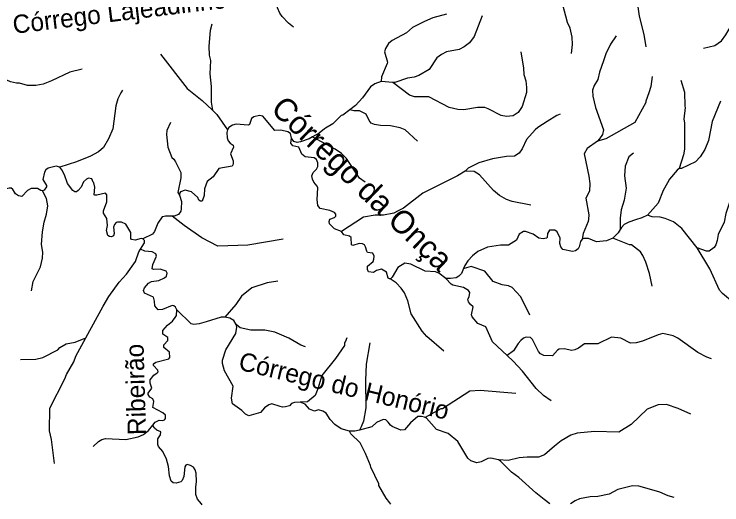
# Model space of a CAD drawing. Extents: x 393 to 446.6, y 8175.5 to 8231.
# Drawn here: x 430.63 to 436.82, y 8175.63 to 8179.91 of the extents above; entities that cross this region are included whole.
import ezdxf
from ezdxf.enums import TextEntityAlignment as Align

# ---------------------------------------------------------------- set-up
doc = ezdxf.new("R2010")
doc.units = 0
doc.header["$LTSCALE"] = 0.064
doc.linetypes.add('LONG_DASHED', pattern=[7.5, 6, -1.5])
doc.layers.add('61', color=7, linetype='Continuous')
doc.layers.add('7', color=7, linetype='Continuous', lineweight=25)
doc.layers.add('9', color=7, linetype='LONG_DASHED', lineweight=25)

msp = doc.modelspace()

# ---------------------------------------------------------------- linework, layer by layer
at = {"layer": '7'}
for points in [[(431.2298, 8179.431), (431.12, 8179.4063), (430.9618, 8179.3287), (430.8875, 8179.2997), (430.8229, 8179.29), (430.7518, 8179.29), (430.6808, 8179.3094), (430.655, 8179.3094), (430.6033, 8179.3223), (430.5387, 8179.3514), (430.5177, 8179.3772), (430.5015, 8179.4402), (430.4983, 8179.5888), (430.4934, 8179.6146), (430.4696, 8179.6566)], [(431.5806, 8179.2495), (431.567, 8179.2242), (431.5398, 8179.1738), (431.5221, 8179.1108), (431.4979, 8178.9106), (431.4591, 8178.8234), (431.4139, 8178.7474), (431.3703, 8178.7103), (431.3009, 8178.6731), (431.1782, 8178.6231), (431.033, 8178.5775)], [(431.033, 8178.5775), (431.0004, 8178.5844), (430.9327, 8178.5666), (430.9117, 8178.5537), (430.8988, 8178.5327), (430.8859, 8178.4697), (430.9181, 8178.4164), (430.9181, 8178.4035), (430.897, 8178.3751), (430.883, 8178.3693)], [(431.7583, 8177.9509), (431.7432, 8177.9521), (431.692, 8177.9393), (431.6593, 8177.9433), (431.6529, 8177.9529), (431.6529, 8178.0062), (431.6093, 8178.0773), (431.5722, 8178.0967), (431.5366, 8178.0967), (431.5269, 8178.0918), (431.5108, 8178.0757), (431.5011, 8178.0531), (431.5075, 8177.9966), (431.5027, 8177.9756), (431.4849, 8177.9691), (431.4688, 8177.9707), (431.4526, 8177.9804), (431.4413, 8178.0224), (431.451, 8178.0676), (431.4446, 8178.129), (431.4139, 8178.1742), (431.4155, 8178.1936), (431.4446, 8178.2743), (431.443, 8178.334), (431.4316, 8178.3502), (431.3558, 8178.3324), (431.3396, 8178.3308), (431.3348, 8178.3357), (431.338, 8178.4003), (431.3299, 8178.4406), (431.3234, 8178.4438), (431.3138, 8178.4746), (431.2831, 8178.4794), (431.2654, 8178.4713), (431.2411, 8178.4471), (431.2185, 8178.4019), (431.1943, 8178.3728), (431.1797, 8178.3599), (431.1652, 8178.3599), (431.1475, 8178.3712), (431.1006, 8178.4326), (431.0748, 8178.5101), (431.0522, 8178.5536), (431.033, 8178.5775)], [(430.883, 8178.3693), (430.8679, 8178.3716), (430.839, 8178.3889), (430.7825, 8178.3906), (430.7518, 8178.3728), (430.7018, 8178.3211), (430.6711, 8178.326), (430.6452, 8178.3437), (430.621, 8178.3857), (430.6146, 8178.3857), (430.613, 8178.3922), (430.5904, 8178.3922), (430.5452, 8178.3809), (430.5257, 8178.3664), (430.4822, 8178.3098), (430.4192, 8178.3098), (430.3578, 8178.3502), (430.2771, 8178.3744), (430.2381, 8178.3946)], [(430.7866, 8177.4953), (430.8003, 8177.5767), (430.8649, 8177.7059), (430.8826, 8177.7802), (430.8842, 8177.8351), (430.8745, 8177.8997), (430.8826, 8178.0127), (430.8955, 8178.0967), (430.9181, 8178.1645), (430.9294, 8178.2388), (430.9165, 8178.3034), (430.883, 8178.3693)], [(431.7389, 8177.8589), (431.7724, 8177.9158), (431.7723, 8177.9358), (431.7583, 8177.9509)], [(431.2609, 8177.0865), (431.4106, 8177.3636), (431.4623, 8177.4476), (431.5527, 8177.5719), (431.6173, 8177.6429), (431.6948, 8177.7511), (431.7239, 8177.8383), (431.7389, 8177.8589)], [(432.0558, 8177.3301), (432.0453, 8177.3539), (432.0291, 8177.3668), (432.0162, 8177.3684), (431.9306, 8177.3329), (431.8935, 8177.3313), (431.8628, 8177.3652), (431.8612, 8177.4056), (431.8515, 8177.4411), (431.7724, 8177.475), (431.7659, 8177.4992), (431.774, 8177.5218), (431.8079, 8177.5622), (431.8338, 8177.5767), (431.8983, 8177.588), (431.9468, 8177.609), (431.9645, 8177.6235), (431.971, 8177.651), (431.9629, 8177.6671), (431.9113, 8177.6849), (431.8531, 8177.6817), (431.8402, 8177.6897), (431.8466, 8177.7269), (431.8773, 8177.7996), (431.8725, 8177.8206), (431.8402, 8177.8367), (431.7756, 8177.8432), (431.7389, 8177.8589)], [(431.8475, 8176.3228), (431.8661, 8176.3507), (431.9016, 8176.3672), (431.9339, 8176.364), (431.9484, 8176.3688), (431.9564, 8176.3818), (431.9564, 8176.4092), (431.9322, 8176.4302), (431.8466, 8176.4771), (431.8547, 8176.5304), (431.845, 8176.553), (431.8208, 8176.5675), (431.8047, 8176.5917), (431.8047, 8176.6014), (431.8386, 8176.645), (431.824, 8176.6886), (431.824, 8176.7192), (431.8547, 8176.7613), (431.8838, 8176.779), (431.8919, 8176.7903), (431.8902, 8176.8032), (431.8515, 8176.8436), (431.8531, 8176.8581), (431.8725, 8176.8743), (431.9872, 8176.9033), (431.9936, 8176.9146), (431.992, 8176.9599), (431.9435, 8177.0018), (431.9419, 8177.0261), (431.9774, 8177.0616), (431.9774, 8177.0874), (431.9338, 8177.1181), (431.9338, 8177.1504), (431.9742, 8177.1956), (432.0178, 8177.2311), (432.0404, 8177.2635), (432.0517, 8177.2812), (432.0558, 8177.3301)], [(430.6888, 8176.8976), (430.8229, 8176.8985), (430.8843, 8176.9146), (431.0167, 8176.9825), (431.0344, 8177.0002), (431.0877, 8177.0325), (431.1685, 8177.0487), (431.2609, 8177.0865)], [(430.9873, 8175.9886), (430.9601, 8176.1977), (430.944, 8176.2752), (430.9472, 8176.4706), (431.078, 8176.7274), (431.0925, 8176.7661), (431.1571, 8176.8759), (431.1733, 8176.9244), (431.2609, 8177.0865)], [(431.3254, 8176.136), (431.3703, 8176.1799), (431.401, 8176.1977), (431.4333, 8176.2074), (431.6109, 8176.1977), (431.7175, 8176.2204), (431.764, 8176.2425), (431.8077, 8176.2768), (431.8475, 8176.3228)], [(432.2769, 8175.6276), (432.27, 8175.636), (432.2358, 8175.6777), (432.2229, 8175.7165), (432.2213, 8175.7811), (432.2277, 8175.8328), (432.2245, 8175.9038), (432.2164, 8175.9329), (432.2003, 8175.9571), (432.1761, 8175.9716), (432.147, 8175.9797), (432.1347, 8175.9749), (432.1244, 8175.9587), (432.1163, 8175.8747), (432.1018, 8175.8408), (432.0905, 8175.8295), (432.0501, 8175.8166), (432.0243, 8175.8198), (432.0065, 8175.8344), (431.9904, 8175.8812), (431.9839, 8175.9619), (431.9645, 8176.0265), (431.9338, 8176.0944), (431.8967, 8176.1363), (431.8902, 8176.1557), (431.8902, 8176.2025), (431.9128, 8176.2397), (431.9161, 8176.2639), (431.8822, 8176.2784), (431.8603, 8176.296), (431.8475, 8176.3228)]]:
    msp.add_lwpolyline(points, dxfattribs=at)
at = {"layer": '9'}
msp.add_line((433.9444, 8179.3147), (433.8419, 8179.3252), dxfattribs=at)
for points in [[(436.1585, 8179.6271), (436.1388, 8179.7341), (436.0984, 8179.8956), (436.0726, 8180.0894), (436.0435, 8180.1717), (436.0176, 8180.225), (435.9886, 8180.3219), (435.9466, 8180.422), (435.8982, 8180.5738), (435.882, 8180.6428)], [(433.0745, 8179.7991), (433.0303, 8179.8342), (432.977, 8179.8907), (432.956, 8179.9214), (432.9367, 8179.9682), (432.9189, 8180.0506), (432.909, 8180.2268), (432.8672, 8180.4074)], [(435.5056, 8179.57), (435.5137, 8179.6468), (435.5106, 8179.7115), (435.4945, 8179.7906), (435.4686, 8179.8407), (435.4299, 8179.9925), (435.4218, 8180.0571), (435.4153, 8180.0651)], [(436.6586, 8179.6162), (436.7565, 8179.6383), (436.8147, 8179.6802), (436.8543, 8179.7331), (436.9359, 8179.8716), (436.9736, 8179.9069), (437.0414, 8179.9424), (437.0661, 8179.9476), (437.1254, 8179.9602), (437.1803, 8179.9892), (437.241, 8180.0438)], [(434.4134, 8179.9117), (434.2915, 8179.8794), (434.2204, 8179.8487), (434.1381, 8179.8084), (434.1155, 8179.7955), (434.0621, 8179.7486), (433.9362, 8179.6824), (433.9055, 8179.6566), (433.878, 8179.6114), (433.8716, 8179.5839), (433.8958, 8179.4935), (433.8942, 8179.4822), (433.8458, 8179.3659), (433.8419, 8179.3252)], [(434.7239, 8179.8977), (434.6532, 8179.718), (434.6128, 8179.6614), (434.5676, 8179.6275), (434.524, 8179.6049), (434.411, 8179.5823), (434.369, 8179.5613), (434.3286, 8179.5306), (434.2608, 8179.4305), (434.172, 8179.3772), (434.13, 8179.361), (434.0702, 8179.353), (433.962, 8179.3158), (433.9444, 8179.3147)], [(432.3621, 8179.8243), (432.3472, 8179.7696), (432.3359, 8179.634), (432.3376, 8179.5549), (432.3488, 8179.5064), (432.344, 8179.3901), (432.3553, 8179.282), (432.3569, 8179.1431), (432.3674, 8179.0748), (432.3677, 8179.0727)], [(435.8948, 8179.7225), (435.8449, 8179.6501), (435.8384, 8179.6372), (435.8078, 8179.5742), (435.8, 8179.5475), (435.7846, 8179.5051), (435.748, 8179.4063), (435.7335, 8179.3417), (435.7028, 8179.2884), (435.6882, 8179.2497), (435.6915, 8179.1948), (435.7141, 8179.0979), (435.7851, 8178.9009), (435.777, 8178.8621), (435.7499, 8178.8233), (435.7313, 8178.8024)], [(431.9133, 8179.5631), (432.1454, 8179.2642), (432.2778, 8179.1592), (432.3677, 8179.0727)], [(435.0618, 8179.5847), (435.0859, 8179.4402), (435.0892, 8179.3853), (435.1053, 8179.3288), (435.1118, 8179.2723), (435.1101, 8179.2271), (435.0746, 8179.1059), (435.0375, 8179.0526), (434.9939, 8179.0252), (434.9374, 8179.0187), (434.889, 8179.0268), (434.7775, 8179.0865), (434.7468, 8179.0962), (434.6823, 8179.0962), (434.5628, 8179.0768), (434.5111, 8179.0801), (434.4368, 8179.0962), (434.2592, 8179.1899), (434.1332, 8179.1899), (434.088, 8179.2044), (433.9444, 8179.3147)], [(436.2099, 8179.3684), (436.1971, 8179.28), (436.182, 8179.2241), (436.1533, 8179.1528), (436.1549, 8179.1415), (436.058, 8178.9671), (435.8062, 8178.8233), (435.7313, 8178.8024)], [(433.8419, 8179.3252), (433.7872, 8179.3042), (433.7489, 8179.2771), (433.6778, 8179.1818), (433.6181, 8179.1156), (433.5665, 8179.0767)], [(436.461, 8179.3372), (436.4908, 8179.2319), (436.494, 8179.1076), (436.4989, 8179.0962), (436.486, 8178.9945), (436.4908, 8178.9622), (436.4912, 8178.732), (436.4842, 8178.6843), (436.4466, 8178.5641)], [(436.8058, 8179.153), (436.733, 8178.9752), (436.7023, 8178.8088), (436.6701, 8178.7313), (436.628, 8178.6651), (436.5877, 8178.6215), (436.465, 8178.565), (436.4466, 8178.5641)], [(432.3677, 8179.0727), (432.4054, 8179.0365), (432.4978, 8178.9009)], [(433.5665, 8179.0767), (433.5067, 8179.0316), (433.4921, 8179.0268), (433.4179, 8178.9541), (433.3557, 8178.916), (433.3468, 8178.9106), (433.2984, 8178.8718), (433.2423, 8178.8405)], [(434.1594, 8178.8027), (434.0499, 8178.9027), (434.008, 8178.919), (433.9242, 8178.9376), (433.8357, 8178.9393), (433.7822, 8178.9498), (433.7555, 8178.9609), (433.7357, 8178.983), (433.7089, 8179.0377), (433.6507, 8179.0668), (433.6029, 8179.0679), (433.5666, 8179.0767), (433.5665, 8179.0767)], [(433.0576, 8178.8287), (433.0483, 8178.8695), (433.0262, 8178.8834), (432.9657, 8178.8992), (432.9124, 8178.896), (432.8075, 8179.0219), (432.7768, 8179.0268), (432.7284, 8179.0171), (432.7073, 8179.001), (432.691, 8178.9492), (432.6806, 8178.9434), (432.5734, 8178.9515), (432.5432, 8178.9434), (432.5106, 8178.9219), (432.4978, 8178.9009)], [(435.4048, 8179.0392), (435.378, 8179.0287), (435.2926, 8178.9751), (435.2119, 8178.9235), (435.186, 8178.9008), (435.1101, 8178.8169), (435.0746, 8178.7362), (435.0472, 8178.699), (435.0052, 8178.6731), (434.9358, 8178.6683), (434.813, 8178.649), (434.6952, 8178.6134), (434.6031, 8178.5682), (434.5768, 8178.5405)], [(432.0003, 8178.9664), (431.9677, 8178.8954), (431.9642, 8178.8628), (431.9758, 8178.7523), (432.013, 8178.6603), (432.0291, 8178.6473), (432.0453, 8178.6215), (432.0905, 8178.5295), (432.0905, 8178.4843), (432.0645, 8178.3563), (432.0787, 8178.3316)], [(432.4978, 8178.9009), (432.4932, 8178.8777), (432.4942, 8178.8331), (432.5039, 8178.8056), (432.5217, 8178.7846), (432.5494, 8178.7676), (432.5506, 8178.7502), (432.5262, 8178.6932), (432.5483, 8178.6315), (432.5483, 8178.6024), (432.539, 8178.5861), (432.4231, 8178.565), (432.3747, 8178.4907), (432.3198, 8178.4503), (432.2972, 8178.3874), (432.2956, 8178.3292), (432.2778, 8178.2799), (432.2615, 8178.2799), (432.2475, 8178.2892), (432.2382, 8178.3113), (432.1846, 8178.3602), (432.1276, 8178.3741), (432.0881, 8178.3607), (432.0787, 8178.3456), (432.0787, 8178.3316)], [(433.495, 8178.0142), (433.4322, 8178.0375), (433.3891, 8178.0805), (433.3856, 8178.1015), (433.3926, 8178.1212), (433.4345, 8178.1375), (433.445, 8178.1492), (433.4461, 8178.1666), (433.4345, 8178.1818), (433.3937, 8178.1992), (433.3076, 8178.2143), (433.2889, 8178.2423), (433.2831, 8178.2946), (433.2868, 8178.3959), (433.2822, 8178.4093), (433.2519, 8178.4465), (433.2403, 8178.471), (433.2368, 8178.5012), (433.2461, 8178.5291), (433.2764, 8178.5582), (433.2868, 8178.5827), (433.2892, 8178.6129), (433.2753, 8178.6431), (433.2567, 8178.6583), (433.1775, 8178.6676), (433.1484, 8178.6885), (433.1228, 8178.7508), (433.0681, 8178.7612), (433.0506, 8178.7868), (433.0576, 8178.8287)], [(433.2423, 8178.8405), (433.2124, 8178.8238), (433.1379, 8178.7971), (433.1066, 8178.7925), (433.0786, 8178.7994), (433.0576, 8178.8287)], [(433.7011, 8178.4443), (433.651, 8178.4804), (433.5381, 8178.6509), (433.495, 8178.6951), (433.438, 8178.7329), (433.245, 8178.839), (433.2423, 8178.8405)], [(435.7313, 8178.8024), (435.6414, 8178.7394), (435.614, 8178.6926), (435.6576, 8178.4988), (435.6656, 8178.4326), (435.6608, 8178.368), (435.6301, 8178.305), (435.6576, 8178.1613), (435.6543, 8178.1225), (435.6511, 8178.1015), (435.6059, 8177.9966), (435.5984, 8177.9481)], [(436.0459, 8178.6985), (436.0064, 8178.6667), (435.9725, 8178.586), (435.9676, 8178.5004), (435.9838, 8178.3922), (435.966, 8178.2873), (435.9386, 8178.2049), (435.9304, 8178.1322), (435.929, 8178.0305)], [(436.4466, 8178.5641), (436.428, 8178.549), (436.3616, 8178.4729), (436.3423, 8178.4406), (436.3051, 8178.3728), (436.2615, 8178.263), (436.1691, 8178.1566)], [(434.5768, 8178.5405), (434.5095, 8178.5004), (434.2059, 8178.3486), (434.0363, 8178.2178), (433.9911, 8178.1936), (433.9524, 8178.1758), (433.8619, 8178.1564), (433.7893, 8178.1581), (433.6875, 8178.1387), (433.495, 8178.0142)], [(435.1481, 8178.2455), (434.9858, 8178.2775), (434.9358, 8178.2937), (434.8744, 8178.3276), (434.8243, 8178.3712), (434.7016, 8178.5085), (434.6548, 8178.5375), (434.5768, 8178.5405)], [(432.0787, 8178.3316), (432.0962, 8178.2769), (432.095, 8178.2118), (432.0904, 8178.192), (432.0718, 8178.1629), (432.0334, 8178.1484), (432.0141, 8178.1487)], [(436.9094, 8178.3369), (436.8541, 8178.171), (436.8396, 8178.0951), (436.7863, 8177.9869), (436.7782, 8177.9352), (436.7653, 8177.8981), (436.7502, 8177.8754), (436.7083, 8177.844), (436.685, 8177.844), (436.6018, 8177.8722)], [(432.0141, 8178.1487), (431.9566, 8178.1495), (431.934, 8178.143), (431.9286, 8178.1414), (431.8891, 8178.0885), (431.8599, 8178.014), (431.8425, 8177.9907), (431.7583, 8177.9509)], [(432.9858, 8177.9473), (432.6767, 8177.8948), (432.4135, 8177.8868), (432.273, 8177.9578), (432.1196, 8178.066), (432.016, 8178.1472), (432.0141, 8178.1487)], [(436.1691, 8178.1566), (436.1205, 8178.1346), (436.0646, 8178.1157), (436.0047, 8178.0965), (435.9663, 8178.0744), (435.9418, 8178.05), (435.929, 8178.0305)], [(436.6018, 8177.8722), (436.4682, 8178.0418), (436.3955, 8178.0983), (436.3229, 8178.129), (436.2809, 8178.1403), (436.2099, 8178.1435), (436.1691, 8178.1566)], [(433.9184, 8177.6022), (433.9133, 8177.6014), (433.904, 8177.6084), (433.8877, 8177.6584), (433.8442, 8177.6865), (433.8006, 8177.6736), (433.7731, 8177.6559), (433.7312, 8177.6623), (433.7231, 8177.6832), (433.7231, 8177.7112), (433.7708, 8177.7519), (433.7778, 8177.774), (433.779, 8177.7996), (433.7697, 8177.8241), (433.7231, 8177.8322), (433.7149, 8177.8427), (433.7056, 8177.8804), (433.6951, 8177.8967), (433.6777, 8177.9072), (433.6497, 8177.9095), (433.5927, 8177.8921), (433.5833, 8177.8967), (433.5787, 8177.9607), (433.5636, 8177.9735), (433.5148, 8177.9863), (433.495, 8178.0142)], [(435.5984, 8177.9481), (435.5821, 8177.9283), (435.5728, 8177.8817), (435.5635, 8177.8643), (435.5391, 8177.8468), (435.5123, 8177.841), (435.4297, 8177.8567), (435.411, 8177.88), (435.404, 8177.9091), (435.4057, 8177.9562), (435.3782, 8178.0127), (435.3605, 8178.0272), (435.3136, 8178.0272), (435.2942, 8177.9966), (435.2926, 8177.9627), (435.2856, 8177.9551), (435.2576, 8177.9516), (435.2204, 8177.9563), (435.1683, 8177.9917), (435.1021, 8178.0159), (435.0843, 8178.0159), (435.0472, 8177.9917), (435.0246, 8177.9401), (434.9535, 8177.8948), (434.8857, 8177.8948), (434.7695, 8177.8787), (434.6871, 8177.8399), (434.6386, 8177.8012), (434.5982, 8177.7576), (434.574, 8177.7188), (434.5621, 8177.6917)], [(435.929, 8178.0305), (435.9116, 8178.004), (435.8662, 8177.9574)], [(435.8662, 8177.9574), (435.8103, 8177.933), (435.7219, 8177.9254), (435.652, 8177.9533), (435.6112, 8177.9533), (435.5984, 8177.9481)], [(436.2099, 8177.5372), (436.1872, 8177.6478), (436.1549, 8177.7479), (436.1291, 8177.806), (436.1081, 8177.8367), (436.029, 8177.898), (436.0112, 8177.898), (435.8662, 8177.9574)], [(437.281, 8176.7799), (437.1981, 8176.8775), (437.1561, 8176.9502), (437.064, 8177.0858), (437.0124, 8177.1892), (436.9655, 8177.341), (436.9155, 8177.3975), (436.8234, 8177.4734), (436.7992, 8177.5025), (436.7137, 8177.6881), (436.6018, 8177.8722)], [(434.407, 8177.6048), (434.3464, 8177.6502), (434.315, 8177.6636), (434.2253, 8177.6682), (434.1009, 8177.7301), (434.0476, 8177.7382), (433.9879, 8177.6994), (433.9378, 8177.6171), (433.9273, 8177.6037), (433.9184, 8177.6022)], [(435.1395, 8177.2851), (435.0617, 8177.4443), (434.9874, 8177.5266), (434.9535, 8177.5396), (434.9002, 8177.5477), (434.8211, 8177.5783), (434.7484, 8177.6688), (434.6274, 8177.7075), (434.5664, 8177.6927), (434.5621, 8177.6917)], [(434.5621, 8177.6917), (434.5432, 8177.6485), (434.521, 8177.6252), (434.4966, 8177.6112), (434.4477, 8177.6036), (434.407, 8177.6048)], [(432.9375, 8177.5798), (432.8446, 8177.5654), (432.7122, 8177.5234), (432.6202, 8177.4492), (432.5717, 8177.3781), (432.476, 8177.2666)], [(434.3879, 8176.9703), (434.2398, 8177.0987), (434.201, 8177.144), (434.1041, 8177.2958), (434.0734, 8177.4088), (434.0444, 8177.4798), (434.017, 8177.5202), (433.9733, 8177.5654), (433.9214, 8177.6002), (433.9184, 8177.6022)], [(434.9416, 8176.9326), (434.8146, 8177.0503), (434.7549, 8177.1811), (434.6871, 8177.2102), (434.6354, 8177.2699), (434.6322, 8177.2877), (434.6451, 8177.3555), (434.6213, 8177.3784), (434.6033, 8177.4006), (434.6001, 8177.425), (434.6095, 8177.4427), (434.6176, 8177.4831), (434.6047, 8177.4992), (434.5611, 8177.5251), (434.4691, 8177.546), (434.4545, 8177.5541), (434.407, 8177.6048)], [(432.476, 8177.2666), (432.4445, 8177.2655), (432.3109, 8177.2252), (432.2504, 8177.2069), (432.2052, 8177.2037), (432.1809, 8177.2086), (432.0558, 8177.3301)], [(432.575, 8177.2015), (432.5528, 8177.2364), (432.5179, 8177.2573), (432.476, 8177.2666)], [(433.1349, 8176.5249), (433.0836, 8176.5222), (433.0578, 8176.5125), (433.04, 8176.4932), (433.0065, 8176.483), (432.978, 8176.4816), (432.9593, 8176.4867), (432.885, 8176.511), (432.8593, 8176.5019), (432.822, 8176.4754), (432.7865, 8176.435), (432.6864, 8176.406), (432.6573, 8176.4189), (432.6234, 8176.4512), (432.5426, 8176.5109), (432.533, 8176.5578), (432.5491, 8176.6644), (432.4716, 8176.7984), (432.4538, 8176.863), (432.4538, 8176.8904), (432.4845, 8176.9825), (432.5717, 8177.1246), (432.5814, 8177.1795), (432.575, 8177.2015)], [(433.1795, 8177.0077), (433.1388, 8177.0228), (433.0352, 8177.0826), (432.9124, 8177.135), (432.8236, 8177.1537), (432.7025, 8177.152), (432.6105, 8177.1746), (432.575, 8177.2015)], [(433.5415, 8177.0864), (433.526, 8177.0471), (433.5196, 8177.0439), (433.5196, 8177.0196), (433.4437, 8176.905), (433.3242, 8176.758), (433.2886, 8176.6402), (433.2645, 8176.5836), (433.1982, 8176.5271), (433.1349, 8176.5249)], [(436.7278, 8176.9023), (436.6862, 8176.9162), (436.6087, 8176.9583), (436.4327, 8177.0842), (436.3939, 8177.102), (436.3035, 8177.123), (436.2615, 8177.1133), (436.1259, 8177.0567), (436.071, 8177.0422), (436.0209, 8177.0406), (435.9353, 8177.0826), (435.8546, 8177.0907), (435.7351, 8177.0325), (435.6172, 8177.0341), (435.5655, 8176.997), (435.5349, 8176.9808), (435.5074, 8176.9744), (435.4412, 8176.9905), (435.396, 8176.9873), (435.3814, 8176.9792), (435.3379, 8176.9292), (435.2636, 8176.9308), (435.2345, 8176.9469), (435.2151, 8176.9663), (435.1634, 8177.0713), (435.1457, 8177.0874), (435.1086, 8177.0906), (435.0859, 8177.0826), (435.0633, 8177.0632), (435.0391, 8177.0374), (434.9987, 8176.9728), (434.9416, 8176.9326)], [(433.7417, 8177.0436), (433.7101, 8176.8565), (433.7037, 8176.7144), (433.7069, 8176.4755), (433.6859, 8176.3592), (433.6653, 8176.3098), (433.6534, 8176.2798)], [(435.327, 8176.536), (435.2587, 8176.582), (435.1947, 8176.6443), (435.0776, 8176.7936), (434.996, 8176.8821), (434.9416, 8176.9326)], [(435.0195, 8176.6), (434.7065, 8176.6272), (434.6177, 8176.6191), (434.377, 8176.4673), (434.3641, 8176.4658), (434.2273, 8176.3901)], [(433.5651, 8176.2699), (433.493, 8176.2903), (433.4372, 8176.3301), (433.3953, 8176.3737), (433.3597, 8176.427), (433.3323, 8176.4463), (433.2935, 8176.456), (433.2596, 8176.4464), (433.2456, 8176.4505), (433.2153, 8176.4644), (433.178, 8176.5075), (433.1349, 8176.5249)], [(436.5464, 8176.4194), (436.4375, 8176.469), (436.3358, 8176.5045), (436.2631, 8176.5013), (436.1646, 8176.4641), (436.0274, 8176.3285), (435.9192, 8176.2623), (435.706, 8176.2671), (435.5542, 8176.2542), (435.4977, 8176.2365), (435.4154, 8176.1864), (435.3556, 8176.1412), (435.27, 8176.0637), (435.2167, 8176.0443), (435.1183, 8176.0443), (435.0488, 8176.0394), (434.9503, 8176.0152), (434.8661, 8176.0196)], [(434.2273, 8176.3901), (434.2187, 8176.3937), (434.1942, 8176.3995), (434.1607, 8176.3979), (434.0977, 8176.343), (434.046, 8176.2832), (434.0121, 8176.2784), (433.9378, 8176.3107), (433.9217, 8176.322), (433.9039, 8176.3495), (433.8813, 8176.3704), (433.8588, 8176.3726), (433.8017, 8176.347), (433.7586, 8176.3075), (433.6534, 8176.2798)], [(434.8661, 8176.0196), (434.7998, 8176.0347), (434.7743, 8176.0314), (434.7162, 8176.0039), (434.6787, 8175.9943), (434.6241, 8176.0104), (434.5983, 8176.0346), (434.511, 8176.1816), (434.4255, 8176.251), (434.3254, 8176.2865), (434.2385, 8176.3855), (434.2273, 8176.3901)], [(433.6534, 8176.2798), (433.6117, 8176.271), (433.5651, 8176.2699)], [(433.9262, 8175.6327), (433.9172, 8175.6446), (433.8861, 8175.6858), (433.8215, 8175.7972), (433.82, 8175.8118), (433.7505, 8175.9555), (433.7489, 8175.9716), (433.7053, 8176.075), (433.6568, 8176.1702), (433.5761, 8176.2477), (433.5651, 8176.2699)], [(435.3147, 8175.6369), (435.2666, 8175.6737), (435.1925, 8175.731), (435.0455, 8175.865), (434.981, 8175.9119), (434.8836, 8176.0102), (434.8661, 8176.0196)], [(436.401, 8175.6927), (436.3499, 8175.7059), (436.276, 8175.7391), (436.1662, 8175.7714), (436.0936, 8175.7908), (436.0371, 8175.794), (435.9095, 8175.7617), (435.8336, 8175.7197), (435.7351, 8175.7003), (435.6689, 8175.6971), (435.5736, 8175.6793), (435.5356, 8175.6618), (435.4968, 8175.6375)]]:
    msp.add_lwpolyline(points, dxfattribs=at)

# ---------------------------------------------------------------- texts
at = {"layer": '61'}
for s, height, rotation, p in [('Córrego Lajeadinho', 0.16, 6.955, (431.5639, 8179.8538)), ('Córrego da Onça', 0.2, 316.265, (433.608, 8178.363)), ('Ribeirão', 0.16, 91.655, (431.776, 8176.6372)), ('Córrego do Honório', 0.16, 346.433, (433.4991, 8176.5898))]:
    msp.add_text(s, height=height, rotation=rotation, dxfattribs=at).set_placement(p, align=Align.CENTER)

doc.saveas('drawing.dxf')
